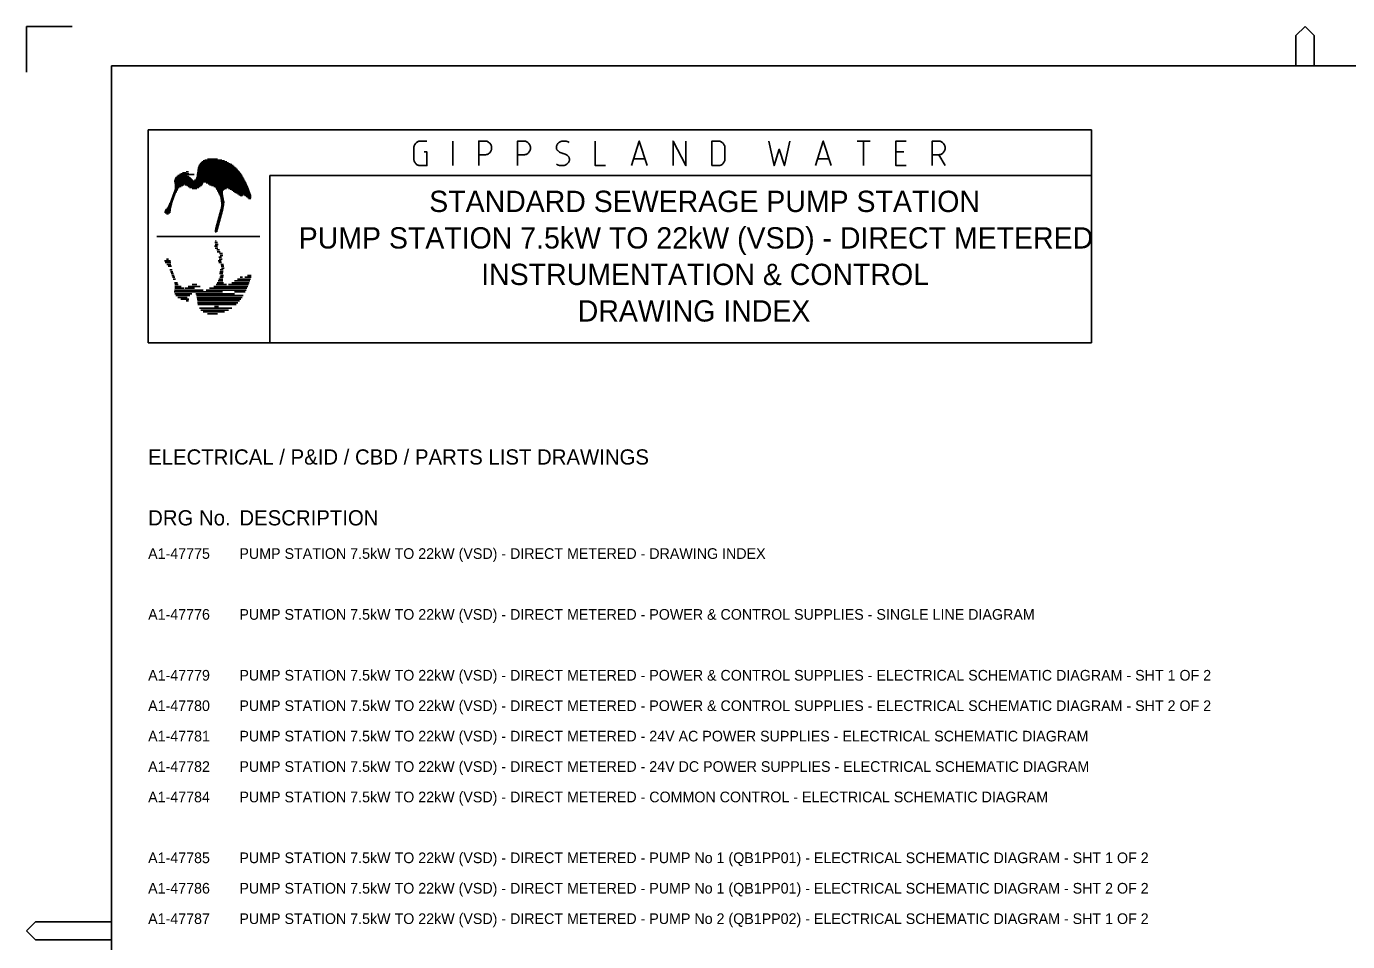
# Model space of a CAD drawing. Extents: x 0 to 841, y 0 to 594.
# Drawn here: x 0 to 434.2, y 293.2 to 594 of the extents above; entities that cross this region are included whole.
import ezdxf

# ---------------------------------------------------------------- set-up
doc = ezdxf.new("R2010")
doc.units = 0
for name, color, linetype in [('A1BORDER', 7, 'Continuous'), ('Level 1', 7, 'Continuous'), ('Level 10', 7, 'Continuous')]:
    doc.layers.add(name, color=color, linetype=linetype)

msp = doc.modelspace()

# ---------------------------------------------------------------- linework, layer by layer
at = {"layer": 'A1BORDER'}
for p, q in [((0, 594), (15, 594)), ((0, 579), (0, 594)), ((417.19, 591), (420.19, 594)), ((417.19, 581), (417.19, 591)), ((423.19, 591), (420.19, 594)), ((423.19, 581), (423.19, 591)), ((28, 581), (829, 581)), ((28, 581), (28, 15)), ((3, 299.76), (0, 296.76)), ((28, 299.76), (3, 299.76)), ((3, 293.76), (0, 296.76)), ((28, 293.76), (3, 293.76))]:
    msp.add_line(p, q, dxfattribs=at)
at = {"layer": 'Level 1'}
for p in [(350, 545), (80, 490)]:
    msp.add_line(p, (350, 490), dxfattribs=at)
at = {"layer": 'Level 10'}
for p, q in [((40, 560), (350, 560)), ((40, 560), (40, 490)), ((350, 545), (350, 560)), ((56.32, 547.08), (69.25, 547.08)), ((56.37, 547.38), (68.95, 547.38)), ((56.44, 547.68), (68.62, 547.68)), ((56.55, 547.98), (68.28, 547.98)), ((56.68, 548.28), (67.89, 548.28)), ((56.84, 548.58), (67.47, 548.58)), ((57.05, 548.88), (67, 548.88)), ((57.3, 549.18), (66.46, 549.18)), ((57.61, 549.48), (65.86, 549.48)), ((58.03, 549.78), (65.14, 549.78)), ((58.59, 550.08), (64.22, 550.08)), ((59.52, 550.38), (62.8, 550.38)), ((48.59, 543.18), (71.88, 543.18)), ((48.61, 542.88), (72.03, 542.88)), ((48.62, 543.48), (54.69, 543.48)), ((48.72, 543.78), (54.33, 543.78)), ((48.85, 544.08), (54.05, 544.08)), ((49.06, 544.38), (53.74, 544.38)), ((49.39, 544.68), (53.35, 544.68)), ((49.81, 544.98), (52.86, 544.98)), ((50.27, 545.28), (55.13, 545.28)), ((50.77, 545.58), (53.34, 545.58)), ((51.31, 545.88), (52.54, 545.88)), ((52.55, 546.18), (53.29, 546.18)), ((55.29, 543.48), (71.71, 543.48)), ((55.63, 543.78), (71.55, 543.78)), ((55.81, 544.08), (71.38, 544.08)), ((55.91, 544.38), (71.2, 544.38)), ((55.95, 544.68), (71.02, 544.68)), ((55.99, 544.98), (70.86, 544.98)), ((56.04, 545.28), (70.66, 545.28)), ((56.06, 545.58), (70.47, 545.58)), ((56.12, 545.88), (70.25, 545.88)), ((56.17, 546.18), (70.03, 546.18)), ((56.22, 546.48), (69.79, 546.48)), ((56.27, 546.78), (69.53, 546.78)), ((80, 545), (350, 545)), ((80, 490), (80, 545)), ((48.02, 538.38), (48.75, 538.38)), ((48.15, 538.68), (48.85, 538.68)), ((48.25, 538.98), (49, 538.98)), ((48.36, 539.28), (49.15, 539.28)), ((48.48, 539.58), (49.3, 539.58)), ((48.58, 539.88), (49.45, 539.88)), ((48.69, 542.58), (58.12, 542.58)), ((48.69, 540.18), (49.6, 540.18)), ((48.75, 542.28), (57.93, 542.28)), ((48.76, 540.48), (49.75, 540.48)), ((48.77, 541.97), (51.82, 541.97)), ((48.8, 541.68), (51.36, 541.68)), ((48.8, 540.78), (49.9, 540.78)), ((48.82, 541.38), (50.84, 541.38)), ((48.82, 541.08), (50.25, 541.08)), ((52.21, 541.97), (57.75, 541.97)), ((52.73, 541.68), (57.51, 541.68)), ((53.14, 541.38), (57.13, 541.38)), ((53.58, 541.08), (56.66, 541.08)), ((54.43, 540.78), (56.01, 540.78)), ((59.08, 542.58), (72.17, 542.58)), ((59.68, 542.28), (72.33, 542.28)), ((60.22, 541.97), (72.46, 541.97)), ((60.8, 541.68), (72.59, 541.68)), ((61.54, 541.38), (72.73, 541.38)), ((62.14, 541.08), (72.85, 541.08)), ((62.32, 540.78), (65.72, 540.78)), ((62.48, 540.48), (65.06, 540.48)), ((62.65, 540.18), (64.78, 540.18)), ((62.8, 539.88), (64.6, 539.88)), ((62.97, 539.58), (64.5, 539.58)), ((63.12, 539.28), (64.47, 539.28)), ((63.25, 538.98), (64.51, 538.98)), ((63.4, 538.68), (64.57, 538.68)), ((63.54, 538.38), (64.61, 538.38)), ((66.36, 540.78), (72.98, 540.78)), ((67, 540.48), (73.11, 540.48)), ((67.47, 540.18), (73.21, 540.18)), ((67.93, 539.88), (73.33, 539.88)), ((68.39, 539.58), (73.44, 539.58)), ((68.86, 539.28), (73.53, 539.28)), ((69.33, 538.98), (73.63, 538.98)), ((69.79, 538.68), (71.11, 538.68)), ((70.25, 538.38), (71.02, 538.38)), ((71.36, 538.68), (73.72, 538.68)), ((71.78, 538.38), (73.81, 538.38)), ((46.15, 534.18), (47.5, 534.18)), ((46.38, 534.47), (47.56, 534.47)), ((46.55, 534.78), (47.63, 534.78)), ((46.69, 535.08), (47.73, 535.08)), ((46.83, 535.38), (47.8, 535.38)), ((46.96, 535.68), (47.88, 535.68)), ((47.09, 535.98), (47.95, 535.98)), ((47.23, 536.26), (48.02, 536.26)), ((47.37, 536.58), (48.12, 536.58)), ((47.48, 536.88), (48.22, 536.88)), ((47.59, 537.18), (48.33, 537.18)), ((47.7, 537.48), (48.43, 537.48)), ((47.81, 537.78), (48.54, 537.78)), ((47.92, 538.08), (48.64, 538.08)), ((63.67, 538.08), (64.66, 538.08)), ((63.75, 537.78), (64.72, 537.78)), ((63.79, 537.48), (64.8, 537.48)), ((63.84, 537.18), (64.86, 537.18)), ((63.85, 534.18), (64.73, 534.18)), ((63.87, 536.88), (64.93, 536.88)), ((63.91, 536.58), (65, 536.58)), ((63.93, 534.47), (64.8, 534.47)), ((63.95, 536.26), (65.06, 536.26)), ((63.98, 534.78), (64.86, 534.78)), ((64, 535.98), (65.03, 535.98)), ((64.03, 535.68), (65, 535.68)), ((64.05, 535.08), (64.92, 535.08)), ((64.08, 535.38), (64.96, 535.38)), ((70.77, 538.08), (70.81, 538.08)), ((72.2, 538.08), (73.89, 538.08)), ((72.62, 537.78), (73.87, 537.78)), ((73.03, 537.48), (73.7, 537.48)), ((45.43, 532.98), (47.32, 532.98)), ((45.45, 533.28), (47.4, 533.28)), ((45.58, 532.68), (47.09, 532.68)), ((45.59, 533.58), (47.43, 533.58)), ((45.85, 533.88), (47.45, 533.88)), ((46.05, 532.38), (46.65, 532.38)), ((62.71, 529.98), (63.66, 529.98)), ((62.8, 530.28), (63.73, 530.28)), ((62.88, 530.58), (63.82, 530.58)), ((62.95, 530.88), (63.9, 530.88)), ((63.04, 531.18), (63.98, 531.18)), ((63.12, 531.48), (64.06, 531.48)), ((63.2, 531.78), (64.15, 531.78)), ((63.28, 532.08), (64.22, 532.08)), ((63.36, 532.38), (64.3, 532.38)), ((63.45, 532.68), (64.39, 532.68)), ((63.52, 532.98), (64.47, 532.98)), ((63.61, 533.28), (64.56, 533.28)), ((63.69, 533.58), (64.61, 533.58)), ((63.77, 533.88), (64.67, 533.88)), ((61.95, 526.98), (62.84, 526.98)), ((61.96, 526.68), (62.76, 526.68)), ((61.98, 527.28), (62.92, 527.28)), ((62.07, 527.58), (63.01, 527.58)), ((62.14, 527.88), (63.09, 527.88)), ((62.19, 526.38), (62.35, 526.38)), ((62.23, 528.18), (63.16, 528.18)), ((62.3, 528.48), (63.25, 528.48)), ((62.38, 528.78), (63.33, 528.78)), ((62.47, 529.08), (63.41, 529.08)), ((62.55, 529.38), (63.49, 529.38)), ((62.63, 529.68), (63.58, 529.68)), ((42.9, 524.97), (76.7, 524.97)), ((61.81, 521.76), (62.76, 521.76)), ((61.95, 522.96), (62.84, 522.96)), ((61.98, 521.16), (62.92, 521.16)), ((62.07, 522.36), (63.01, 522.36)), ((62.19, 523.56), (62.35, 523.56)), ((45.43, 516.96), (47.32, 516.96)), ((46.05, 517.56), (46.65, 517.56)), ((62.55, 520.56), (63.49, 520.56)), ((62.71, 519.96), (63.66, 519.96)), ((63.01, 516.96), (63.95, 516.96)), ((63.2, 518.16), (64.15, 518.16)), ((63.36, 517.56), (64.3, 517.56)), ((63.49, 519.36), (64.44, 519.36)), ((63.66, 518.76), (64.6, 518.76)), ((45.59, 516.36), (47.43, 516.36)), ((46.15, 515.76), (47.5, 515.76)), ((46.55, 515.16), (47.63, 515.16)), ((47.09, 513.96), (47.95, 513.96)), ((47.37, 513.36), (48.12, 513.36)), ((47.59, 512.76), (48.33, 512.76)), ((63.18, 516.36), (64.11, 516.36)), ((63.49, 512.76), (64.53, 512.76)), ((63.58, 513.36), (64.66, 513.36)), ((63.66, 513.96), (64.69, 513.96)), ((63.85, 515.76), (64.73, 515.76)), ((63.98, 515.16), (64.86, 515.16)), ((64.08, 514.56), (64.96, 514.56)), ((47.81, 512.16), (48.54, 512.16)), ((48.02, 511.56), (48.75, 511.56)), ((48.25, 510.96), (49, 510.96)), ((48.69, 509.76), (49.6, 509.76)), ((48.8, 509.16), (49.9, 509.16)), ((48.82, 508.56), (50.84, 508.56)), ((53.14, 508.56), (57.13, 508.56)), ((54.43, 509.16), (56.01, 509.16)), ((61.54, 508.56), (72.73, 508.56)), ((62.32, 509.16), (65.72, 509.16)), ((62.65, 509.76), (64.78, 509.76)), ((62.97, 510.36), (64.5, 510.36)), ((63.25, 510.96), (64.51, 510.96)), ((63.54, 511.56), (64.61, 511.56)), ((63.75, 512.16), (64.72, 512.16)), ((66.36, 509.16), (72.98, 509.16)), ((67.47, 509.76), (73.21, 509.76)), ((68.39, 510.36), (73.44, 510.36)), ((69.33, 510.96), (73.63, 510.96)), ((70.25, 511.56), (71.02, 511.56)), ((71.78, 511.56), (73.81, 511.56)), ((72.62, 512.16), (73.87, 512.16)), ((48.59, 506.76), (64.41, 506.76)), ((48.69, 507.36), (58.12, 507.36)), ((48.72, 506.16), (54.33, 506.16)), ((48.77, 507.98), (51.82, 507.98)), ((49.06, 505.56), (53.74, 505.56)), ((49.81, 504.96), (52.86, 504.96)), ((50.77, 504.36), (53.34, 504.36)), ((52.21, 507.98), (55.27, 507.98)), ((52.55, 503.76), (53.29, 503.76)), ((55.63, 506.16), (68.34, 506.16)), ((55.91, 505.56), (71.2, 505.56)), ((55.99, 504.96), (70.86, 504.96)), ((56.06, 504.36), (70.47, 504.36)), ((56.17, 503.76), (70.03, 503.76)), ((59.08, 507.36), (72.17, 507.36)), ((60.22, 507.98), (72.46, 507.98)), ((68.41, 506.76), (71.88, 506.76)), ((56.27, 503.16), (69.53, 503.16)), ((56.37, 502.56), (68.95, 502.56)), ((56.84, 501.36), (67.47, 501.36)), ((57.3, 500.76), (66.46, 500.76)), ((58.03, 500.16), (65.14, 500.16)), ((59.52, 499.56), (62.8, 499.56)), ((61.86, 501.96), (63.16, 501.96)), ((80, 490), (40, 490))]:
    msp.add_line(p, q, dxfattribs=at)
for points in [[(130.74, 552.73), (131.59, 552.73), (131.59, 548.24), (129.46, 548.24), (129.27, 548.24), (129.09, 548.27), (128.92, 548.32), (128.72, 548.38), (128.56, 548.45), (128.4, 548.54), (128.23, 548.64), (128.09, 548.76), (127.96, 548.9), (127.83, 549.05), (127.72, 549.2), (127.62, 549.37), (127.53, 549.53), (127.47, 549.71), (127.41, 549.9), (127.36, 550.09), (127.33, 550.28), (127.33, 550.49), (127.33, 554.08), (127.33, 554.27), (127.36, 554.47), (127.41, 554.64), (127.47, 554.84), (127.53, 555), (127.62, 555.19), (127.72, 555.35), (127.83, 555.5), (127.96, 555.65), (128.09, 555.78), (128.23, 555.9), (128.4, 556.01), (128.56, 556.1), (128.72, 556.18), (128.92, 556.24), (129.09, 556.28), (129.27, 556.31), (129.46, 556.31), (131.59, 556.31)], [(140.11, 548.24), (140.11, 556.31)], [(148.63, 548.24), (148.63, 556.31), (150.76, 556.31), (150.94, 556.31), (151.12, 556.28), (151.3, 556.24), (151.48, 556.18), (151.65, 556.1), (151.81, 556.01), (151.97, 555.9), (152.11, 555.78), (152.26, 555.65), (152.38, 555.5), (152.49, 555.35), (152.59, 555.19), (152.68, 555), (152.75, 554.84), (152.81, 554.64), (152.84, 554.47), (152.88, 554.27), (152.89, 554.08), (152.88, 553.87), (152.84, 553.67), (152.81, 553.49), (152.75, 553.29), (152.68, 553.13), (152.59, 552.95), (152.49, 552.78), (152.38, 552.63), (152.26, 552.49), (152.11, 552.35), (151.97, 552.23), (151.81, 552.12), (151.65, 552.03), (151.48, 551.96), (151.3, 551.9), (151.12, 551.86), (150.94, 551.83), (150.76, 551.83), (148.63, 551.83)], [(161.4, 548.24), (161.4, 556.31), (163.53, 556.31), (163.71, 556.31), (163.88, 556.28), (164.06, 556.24), (164.25, 556.18), (164.41, 556.1), (164.58, 556.01), (164.74, 555.9), (164.89, 555.78), (165.03, 555.65), (165.15, 555.5), (165.27, 555.35), (165.35, 555.19), (165.44, 555), (165.52, 554.84), (165.58, 554.64), (165.62, 554.47), (165.64, 554.27), (165.66, 554.08), (165.64, 553.87), (165.62, 553.67), (165.58, 553.49), (165.52, 553.29), (165.44, 553.13), (165.35, 552.95), (165.27, 552.78), (165.15, 552.63), (165.03, 552.49), (164.89, 552.35), (164.74, 552.23), (164.58, 552.12), (164.41, 552.03), (164.25, 551.96), (164.06, 551.9), (163.88, 551.86), (163.71, 551.83), (163.53, 551.83), (161.4, 551.83)], [(174.18, 548.69), (174.5, 548.54), (174.85, 548.4), (175.18, 548.32), (175.54, 548.25), (175.9, 548.24), (176.26, 548.24), (176.31, 548.24), (176.55, 548.27), (176.77, 548.32), (177, 548.39), (177.22, 548.48), (177.43, 548.6), (177.58, 548.69), (177.72, 548.79), (177.85, 548.91), (177.97, 549.03), (178.08, 549.17), (178.16, 549.32), (178.25, 549.49), (178.33, 549.63), (178.38, 549.82), (178.42, 549.98), (178.44, 550.04), (178.45, 550.16), (178.45, 550.28), (178.45, 550.41), (178.44, 550.53), (178.41, 550.65), (178.38, 550.79), (178.33, 550.89), (178.27, 551.01), (178.21, 551.13), (178.13, 551.23), (178.06, 551.32), (178.02, 551.38), (177.78, 551.59), (177.53, 551.76), (177.28, 551.91), (177.01, 552.05), (176.72, 552.17), (176.43, 552.25), (176.31, 552.27), (176.02, 552.35), (175.74, 552.44), (175.45, 552.56), (175.18, 552.71), (174.94, 552.89), (174.7, 553.09), (174.59, 553.18), (174.5, 553.26), (174.43, 553.36), (174.37, 553.46), (174.3, 553.57), (174.25, 553.69), (174.21, 553.81), (174.19, 553.93), (174.16, 554.06), (174.15, 554.18), (174.15, 554.32), (174.16, 554.44), (174.18, 554.52), (174.21, 554.69), (174.27, 554.87), (174.33, 555.03), (174.41, 555.19), (174.5, 555.34), (174.61, 555.49), (174.73, 555.61), (174.85, 555.73), (174.99, 555.85), (175.03, 555.86), (175.22, 556), (175.45, 556.1), (175.66, 556.18), (175.9, 556.25), (176.12, 556.28), (176.31, 556.31), (176.66, 556.33), (177.03, 556.29), (177.37, 556.24), (177.73, 556.14), (178.06, 556.02), (178.41, 555.88)], [(186.94, 556.31), (186.94, 548.24), (190.34, 548.24)], [(198.87, 548.24), (201.41, 556.31), (203.98, 548.24)], [(212.49, 548.24), (212.49, 556.31), (216.75, 548.24), (216.75, 556.31)], [(225.28, 548.24), (225.28, 556.31), (227.41, 556.31), (227.59, 556.31), (227.77, 556.28), (227.95, 556.24), (228.13, 556.18), (228.3, 556.1), (228.46, 556.01), (228.62, 555.9), (228.76, 555.78), (228.91, 555.65), (229.03, 555.5), (229.13, 555.35), (229.24, 555.19), (229.33, 555), (229.41, 554.84), (229.47, 554.64), (229.5, 554.47), (229.53, 554.27), (229.54, 554.08), (229.54, 550.49), (229.53, 550.28), (229.5, 550.09), (229.47, 549.9), (229.41, 549.71), (229.33, 549.53), (229.24, 549.37), (229.13, 549.2), (229.03, 549.05), (228.91, 548.9), (228.76, 548.76), (228.62, 548.64), (228.46, 548.54), (228.3, 548.45), (228.13, 548.38), (227.95, 548.32), (227.77, 548.27), (227.59, 548.24), (227.41, 548.24), (225.28, 548.24)], [(244.02, 556.31), (245.71, 548.24), (247.42, 553.62), (249.12, 548.24), (250.83, 556.31)], [(259.33, 548.24), (261.88, 556.31), (264.44, 548.24)], [(272.97, 556.31), (277.23, 556.31)], [(275.1, 556.31), (275.1, 548.24)], [(289.13, 548.24), (285.73, 548.24), (285.73, 556.31), (289.13, 556.31)], [(297.67, 548.24), (297.67, 556.31), (299.8, 556.31), (299.98, 556.31), (300.16, 556.28), (300.34, 556.24), (300.52, 556.18), (300.69, 556.1), (300.85, 556.01), (301.01, 555.9), (301.15, 555.78), (301.3, 555.65), (301.42, 555.5), (301.53, 555.35), (301.63, 555.19), (301.72, 555), (301.8, 554.84), (301.84, 554.64), (301.88, 554.47), (301.92, 554.27), (301.92, 554.08), (301.92, 553.87), (301.88, 553.67), (301.84, 553.49), (301.8, 553.29), (301.72, 553.13), (301.63, 552.95), (301.53, 552.78), (301.42, 552.63), (301.3, 552.49), (301.15, 552.35), (301.01, 552.23), (300.85, 552.12), (300.69, 552.03), (300.52, 551.96), (300.34, 551.9), (300.16, 551.86), (299.98, 551.83), (299.8, 551.83), (297.67, 551.83)], [(288.3, 552.73), (285.73, 552.73)], [(299.8, 551.83), (301.92, 548.24)], [(199.72, 550.49), (203.12, 550.49)], [(260.19, 550.49), (263.59, 550.49)]]:
    msp.add_lwpolyline(points, dxfattribs=at)

# ---------------------------------------------------------------- texts
at = {"layer": 'Level 1'}
for s, height, p in [('STANDARD SEWERAGE PUMP STATION', 7, (132.37, 533)), ('PUMP STATION 7.5kW TO 22kW (VSD) - DIRECT METERED', 7, (89.49, 521)), ('INSTRUMENTATION & CONTROL', 7, (149.46, 509)), ('DRAWING INDEX', 7, (181.18, 497)), ('ELECTRICAL / P&ID / CBD / PARTS LIST DRAWINGS', 5, (40, 450)), ('DRG No.', 5, (40, 430)), ('DESCRIPTION', 5, (70, 430)), ('A1-47775', 3.5, (40, 419)), ('PUMP STATION 7.5kW TO 22kW (VSD) - DIRECT METERED - DRAWING INDEX', 3.5, (70, 419)), ('A1-47776', 3.5, (40, 399)), ('PUMP STATION 7.5kW TO 22kW (VSD) - DIRECT METERED - POWER & CONTROL SUPPLIES - SINGLE LINE DIAGRAM', 3.5, (70, 399)), ('A1-47779', 3.5, (40, 379)), ('PUMP STATION 7.5kW TO 22kW (VSD) - DIRECT METERED - POWER & CONTROL SUPPLIES - ELECTRICAL SCHEMATIC DIAGRAM - SHT 1 OF 2', 3.49998, (70, 379)), ('A1-47780', 3.5, (40, 369)), ('PUMP STATION 7.5kW TO 22kW (VSD) - DIRECT METERED - POWER & CONTROL SUPPLIES - ELECTRICAL SCHEMATIC DIAGRAM - SHT 2 OF 2', 3.49998, (70, 369)), ('A1-47781', 3.5, (40, 359)), ('PUMP STATION 7.5kW TO 22kW (VSD) - DIRECT METERED - 24V AC POWER SUPPLIES - ELECTRICAL SCHEMATIC DIAGRAM', 3.49998, (70, 359)), ('A1-47782', 3.5, (40, 349)), ('PUMP STATION 7.5kW TO 22kW (VSD) - DIRECT METERED - 24V DC POWER SUPPLIES - ELECTRICAL SCHEMATIC DIAGRAM', 3.49998, (70, 349)), ('A1-47784', 3.5, (40, 339)), ('PUMP STATION 7.5kW TO 22kW (VSD) - DIRECT METERED - COMMON CONTROL - ELECTRICAL SCHEMATIC DIAGRAM', 3.5, (70, 339)), ('A1-47785', 3.5, (40, 319)), ('PUMP STATION 7.5kW TO 22kW (VSD) - DIRECT METERED - PUMP No 1 (QB1PP01) - ELECTRICAL SCHEMATIC DIAGRAM - SHT 1 OF 2', 3.49998, (70, 319)), ('PUMP STATION 7.5kW TO 22kW (VSD) - DIRECT METERED - PUMP No 1 (QB1PP01) - ELECTRICAL SCHEMATIC DIAGRAM - SHT 2 OF 2', 3.49998, (70, 309)), ('A1-47786', 3.5, (40, 309)), ('A1-47787', 3.5, (40, 299)), ('PUMP STATION 7.5kW TO 22kW (VSD) - DIRECT METERED - PUMP No 2 (QB1PP02) - ELECTRICAL SCHEMATIC DIAGRAM - SHT 1 OF 2', 3.49998, (70, 299))]:
    msp.add_text(s, height=height, dxfattribs=at).set_placement(p)

doc.saveas('drawing.dxf')
